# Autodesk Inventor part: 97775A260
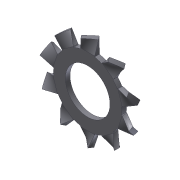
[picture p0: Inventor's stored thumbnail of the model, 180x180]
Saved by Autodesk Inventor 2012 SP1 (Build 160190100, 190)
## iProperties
Created: 2012-03
Part Number: 97775A260
Material: Stainless Steel
Document SubType Name: Modeling
Designer: jdh
Density: 8.08 g/cm^3
Mass: 0.167164 g
Surface Area: 1.1565 cm^2
Volume: 0.0206886 cm^3
Translation Standard: STEP AP203
FileName: 97775A260.step
PreProcessor: SolidWorks 2007
PostProcessor: Build: 190, Release: 2012 SP1 - Date: Mon 08/08/2011
Sent Units: inch
Uncertainty: 1e-05
Author: jdh
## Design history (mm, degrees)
node "97775A2601"
node "NONE"
node "Base1"
